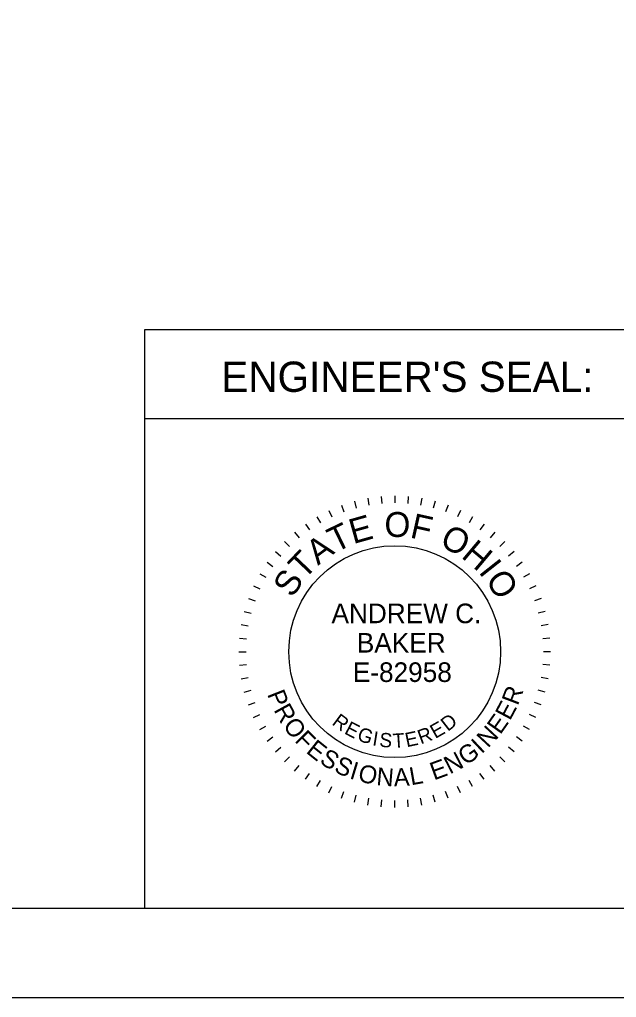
# Model space of a CAD drawing. Extents: x -8.3 to 34, y 0 to 22.
# Drawn here: x 6.65 to 10, y 0 to 5.49 of the extents above; entities that cross this region are included whole.
import ezdxf

# ---------------------------------------------------------------- set-up
doc = ezdxf.new("R2010")
doc.units = 0
for name, color, linetype in [('SH_Border', 7, 'Continuous'), ('SH_Cut_Line', 7, 'Continuous'), ('SH_Data', 7, 'Continuous'), ('SH_Text', 7, 'Continuous')]:
    doc.layers.add(name, color=color, linetype=linetype)

msp = doc.modelspace()

# ---------------------------------------------------------------- linework, layer by layer
at = {"layer": 'SH_Border'}
msp.add_lwpolyline([(1.5, 21.5), (33.5, 21.5), (33.5, 0.5), (1.5, 0.5)], close=True, dxfattribs=at)
at = {"layer": 'SH_Cut_Line'}
msp.add_lwpolyline([(0, 0), (34, 0), (34, 22), (0, 22)], close=True, dxfattribs=at)
at = {"layer": 'SH_Data'}
for p, q in [((7.35, 0.5), (7.35, 3.75)), ((7.35, 3.75), (10.15, 3.75)), ((7.35, 3.25), (10.15, 3.25)), ((8.6026, 2.803), (8.6095, 2.7636)), ((8.6782, 2.813), (8.6817, 2.7732)), ((8.7545, 2.8163), (8.7545, 2.7763)), ((8.8308, 2.813), (8.8273, 2.7732)), ((8.9065, 2.803), (8.8995, 2.7636)), ((8.4552, 2.7636), (8.4689, 2.726)), ((8.528, 2.7865), (8.5384, 2.7479)), ((8.981, 2.7865), (8.9706, 2.7479)), ((9.0538, 2.7636), (9.0401, 2.726)), ((8.317, 2.6991), (8.337, 2.6645)), ((8.3847, 2.7343), (8.4016, 2.6981)), ((9.1243, 2.7343), (9.1074, 2.6981)), ((9.192, 2.6991), (9.172, 2.6645)), ((8.2526, 2.6581), (8.2756, 2.6253)), ((9.2564, 2.6581), (9.2334, 2.6253)), ((8.1921, 2.6116), (8.2178, 2.581)), ((9.317, 2.6116), (9.2912, 2.581)), ((8.1358, 2.56), (8.1641, 2.5318)), ((9.3732, 2.56), (9.3449, 2.5318)), ((8.0842, 2.5038), (8.1149, 2.4781)), ((9.4248, 2.5038), (9.3942, 2.4781)), ((8.0378, 2.4432), (8.0705, 2.4203)), ((9.4713, 2.4432), (9.4385, 2.4203)), ((7.9967, 2.3788), (8.0314, 2.3588)), ((9.5123, 2.3788), (9.4776, 2.3588)), ((7.9615, 2.3111), (7.9977, 2.2942)), ((9.5475, 2.3111), (9.5113, 2.2942)), ((7.9323, 2.2406), (7.9699, 2.2269)), ((9.5767, 2.2406), (9.5392, 2.2269)), ((7.9093, 2.1678), (7.948, 2.1574)), ((9.5997, 2.1678), (9.5611, 2.1574)), ((7.8928, 2.0933), (7.9322, 2.0863)), ((9.6162, 2.0933), (9.5768, 2.0863)), ((7.8828, 2.0176), (7.9227, 2.0141)), ((9.6262, 2.0176), (9.5863, 2.0141)), ((7.8795, 1.9413), (7.9195, 1.9413)), ((9.6295, 1.9413), (9.5895, 1.9413)), ((7.8828, 1.8651), (7.9227, 1.8686)), ((9.6262, 1.8651), (9.5863, 1.8686)), ((7.8928, 1.7894), (7.9322, 1.7963)), ((9.6162, 1.7894), (9.5768, 1.7963)), ((7.9093, 1.7149), (7.948, 1.7252)), ((9.5997, 1.7149), (9.5611, 1.7252)), ((7.9323, 1.6421), (7.9699, 1.6557)), ((9.5767, 1.6421), (9.5392, 1.6557)), ((7.9615, 1.5715), (7.9977, 1.5884)), ((9.5475, 1.5715), (9.5113, 1.5884)), ((7.9967, 1.5038), (8.0314, 1.5238)), ((9.5123, 1.5038), (9.4776, 1.5238)), ((8.0378, 1.4394), (8.0705, 1.4624)), ((9.4713, 1.4394), (9.4385, 1.4624)), ((8.0842, 1.3789), (8.1149, 1.4046)), ((9.4248, 1.3789), (9.3942, 1.4046)), ((8.1358, 1.3226), (8.1641, 1.3509)), ((9.3732, 1.3226), (9.3449, 1.3509)), ((8.1921, 1.271), (8.2178, 1.3017)), ((9.317, 1.271), (9.2912, 1.3017)), ((8.2526, 1.2246), (8.2756, 1.2573)), ((8.317, 1.1836), (8.337, 1.2182)), ((9.192, 1.1836), (9.172, 1.2182)), ((9.2564, 1.2246), (9.2334, 1.2573)), ((8.3847, 1.1483), (8.4016, 1.1846)), ((8.4552, 1.1191), (8.4689, 1.1567)), ((9.0538, 1.1191), (9.0401, 1.1567)), ((9.1243, 1.1483), (9.1074, 1.1846)), ((8.528, 1.0961), (8.5384, 1.1348)), ((8.6026, 1.0796), (8.6095, 1.119)), ((8.6782, 1.0697), (8.6817, 1.1095)), ((8.7545, 1.0663), (8.7545, 1.1063)), ((8.8308, 1.0697), (8.8273, 1.1095)), ((8.9065, 1.0796), (8.8995, 1.119)), ((8.981, 1.0961), (8.9706, 1.1348))]:
    msp.add_line(p, q, dxfattribs=at)
msp.add_circle((8.7545, 1.9413), 0.595, dxfattribs=at)

# ---------------------------------------------------------------- texts
for s, height, rotation, p in [('E', 0.14, 15.7571, (8.5214, 2.5447)), ('O', 0.14, 359.7812, (8.6965, 2.5856)), ('F', 0.14, 347.4362, (8.8356, 2.5831)), ('T', 0.14, 25.7167, (8.4206, 2.4953)), ('O', 0.14, 332.2586, (9.0008, 2.5394)), ('A', 0.14, 36.4747, (8.3231, 2.4232)), ('H', 0.14, 319.9136, (9.123, 2.473)), ('T', 0.14, 46.4344, (8.2462, 2.3414)), ('I', 0.14, 308.367, (9.2219, 2.3885)), ('S', 0.14, 57.1924, (8.1805, 2.2394)), ('O', 0.14, 303.1491, (9.2606, 2.3441)), ('P', 0.1, 291.494, (8.0369, 1.7032)), ('R', 0.1, 69.2322, (9.4458, 1.6349)), ('R', 0.1, 298.7311, (8.0726, 1.6147)), ('E', 0.1, 61.9951, (9.4017, 1.5503)), ('R', 0.08, 323.2378, (8.3973, 1.5354)), ('E', 0.1, 54.758, (9.3473, 1.4719)), ('O', 0.1, 306.4666, (8.1228, 1.5259)), ('E', 0.08, 332.4256, (8.4667, 1.4836)), ('E', 0.08, 29.4558, (8.9819, 1.4508)), ('D', 0.08, 38.0378, (9.0526, 1.4902)), ('F', 0.1, 314.7068, (8.1888, 1.4396)), ('G', 0.08, 341.0076, (8.5382, 1.4457)), ('I', 0.08, 350.8085, (8.6258, 1.4162)), ('S', 0.08, 355.1352, (8.6657, 1.4079)), ('T', 0.08, 3.7172, (8.7463, 1.4007)), ('E', 0.08, 11.686, (8.8214, 1.4047)), ('R', 0.08, 20.268, (8.9007, 1.4207)), ('N', 0.1, 47.0224, (9.2787, 1.3964)), ('E', 0.1, 321.4393, (8.2515, 1.3767)), ('I', 0.1, 43.287, (9.2421, 1.3634)), ('S', 0.1, 328.6764, (8.3267, 1.3179)), ('N', 0.1, 27.3113, (9.0642, 1.2515)), ('G', 0.1, 35.0469, (9.1542, 1.2995)), ('S', 0.1, 335.9134, (8.4086, 1.2689)), ('I', 0.1, 343.1505, (8.4961, 1.2307)), ('E', 0.1, 20.0742, (8.9748, 1.218)), ('O', 0.1, 346.8859, (8.5429, 1.2154)), ('N', 0.1, 355.1261, (8.6491, 1.1926)), ('A', 0.1, 2.8617, (8.7509, 1.1852)), ('L', 0.1, 10.0987, (8.8462, 1.1908))]:
    msp.add_text(s, height=height, rotation=rotation, dxfattribs=at).set_placement(p)
for s, p in [('ANDREW C.', (8.3995, 2.1013)), ('BAKER', (8.5419, 1.9363)), ('E-82958', (8.5192, 1.7713))]:
    msp.add_text(s, height=0.11, dxfattribs=at).set_placement(p)
at = {"layer": 'SH_Text'}
msp.add_text("ENGINEER'S SEAL:", height=0.17, dxfattribs=at).set_placement((7.7808, 3.4))

doc.saveas('drawing.dxf')
